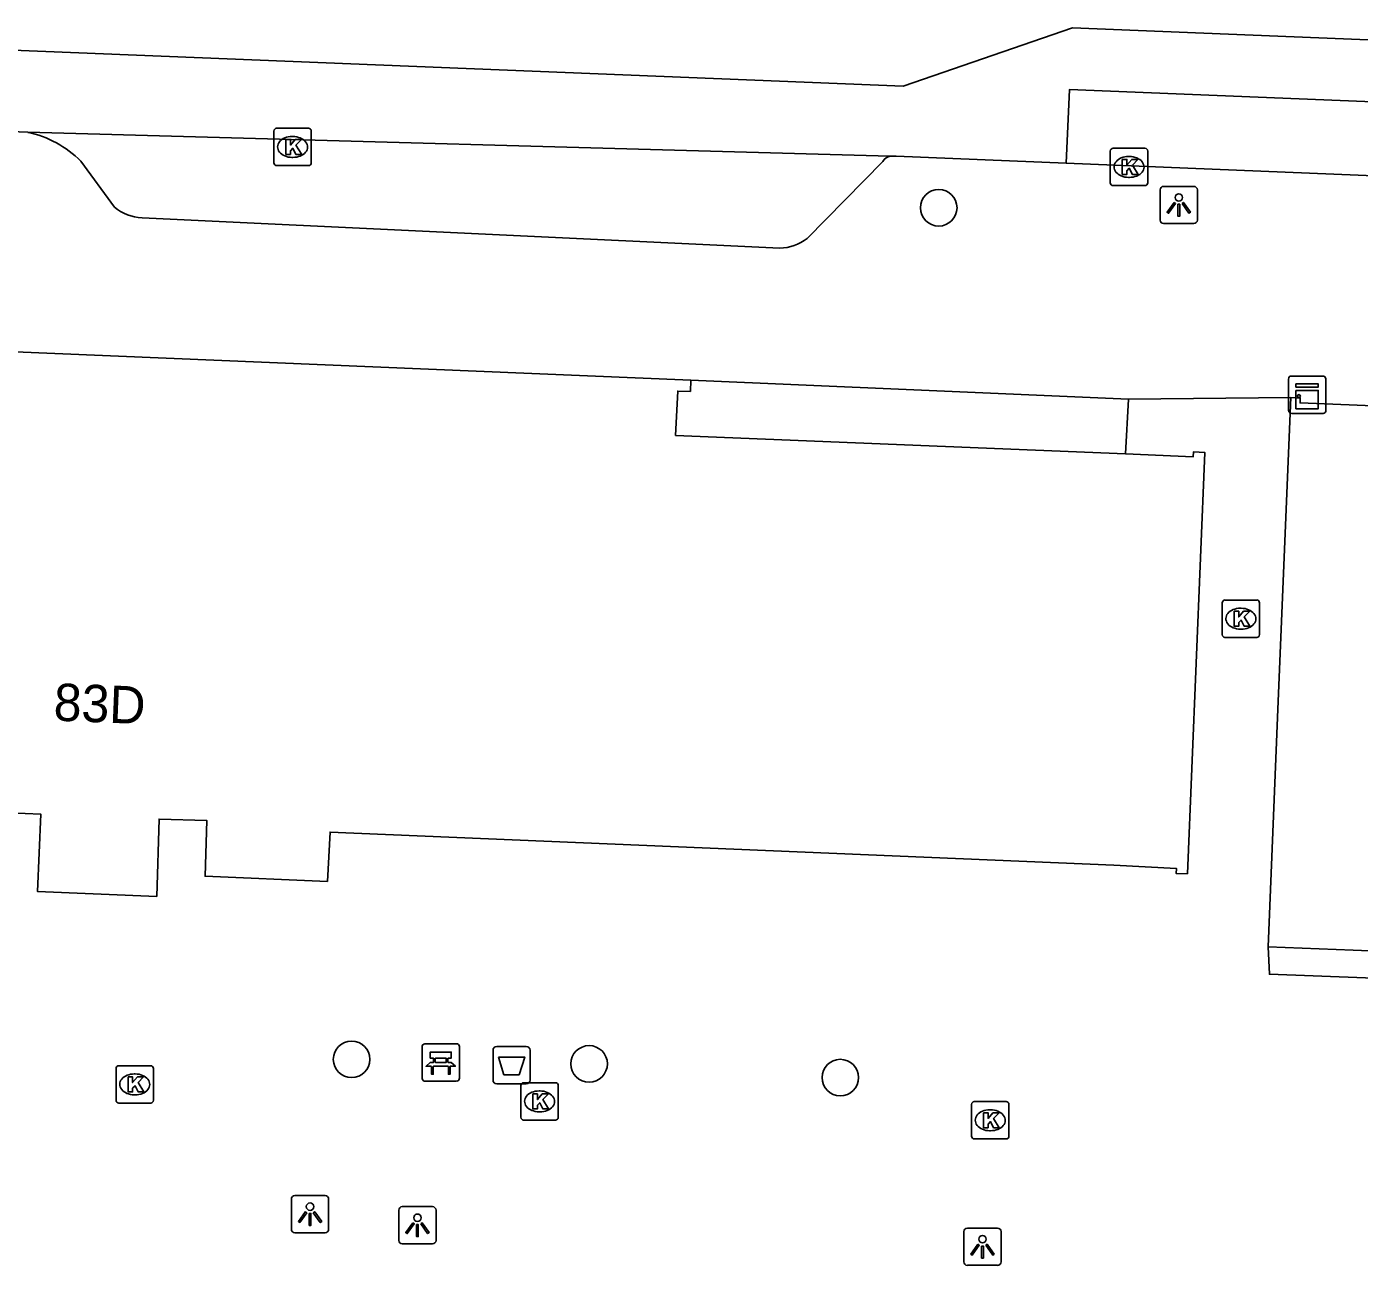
# Model space of a CAD drawing. Extents: x 160891 to 161384, y 386490 to 386907.
# Drawn here: x 161012.2 to 161047.88, y 386870.79 to 386903.93 of the extents above; entities that cross this region are included whole.
import ezdxf

# ---------------------------------------------------------------- set-up
doc = ezdxf.new("R2010")
doc.units = 0
for name, color, linetype in [('IMGEO_Afvalbak', 7, 'Continuous'), ('IMGEO_Bank', 7, 'Continuous'), ('IMGEO_Boom', 7, 'Continuous'), ('IMGEO_Kast', 7, 'Continuous'), ('IMGEO_Kolk', 7, 'Continuous'), ('IMGEO_Lichtpunt', 7, 'Continuous'), ('IMGEO_Pand', 7, 'Continuous'), ('IMGEO_Pand_nummerreeks', 7, 'Continuous'), ('IMGEO_Rijbaan_lokaal_gesloten', 7, 'Continuous'), ('IMGEO_Voetpad_open', 7, 'Continuous')]:
    doc.layers.add(name, color=color, linetype=linetype)

msp = doc.modelspace()

# ---------------------------------------------------------------- linework, layer by layer
at = {"layer": 'IMGEO_Afvalbak'}
for p, q in [((161024.689, 386875.746), (161024.689, 386876.546)), ((161024.689, 386876.546), (161024.689, 386875.746)), ((161024.789, 386876.646), (161025.579, 386876.646)), ((161025.579, 386876.646), (161024.789, 386876.646)), ((161025.679, 386876.546), (161025.679, 386875.746)), ((161025.679, 386875.746), (161025.679, 386876.546)), ((161025.579, 386875.646), (161024.789, 386875.646)), ((161024.789, 386875.646), (161025.579, 386875.646))]:
    msp.add_line(p, q, dxfattribs=at)
msp.add_lwpolyline([(161024.832, 386876.36), (161025.536, 386876.36), (161025.387, 386875.89), (161024.981, 386875.89), (161024.832, 386876.36)], dxfattribs=at)
for centre, start, end in [((161024.789, 386876.546), 90, 180), ((161024.789, 386876.546), 90, 180), ((161025.579, 386876.546), 0, 90), ((161025.579, 386876.546), 360, 90), ((161024.789, 386875.746), 180, 270), ((161024.789, 386875.746), 180, 270), ((161025.579, 386875.746), 270, 0), ((161025.579, 386875.746), 270, 0)]:
    msp.add_arc(centre, 0.1, start, end, dxfattribs=at)
at = {"layer": 'IMGEO_Bank'}
for p, q in [((161022.79, 386875.792), (161022.79, 386876.633)), ((161022.79, 386876.633), (161022.79, 386875.792)), ((161022.865, 386876.717), (161023.706, 386876.717)), ((161023.706, 386876.717), (161022.865, 386876.717)), ((161023.79, 386876.642), (161023.79, 386875.801)), ((161023.79, 386875.801), (161023.79, 386876.642)), ((161023.099, 386876.223), (161023.099, 386876.329)), ((161023.143, 386876.329), (161023.143, 386876.223)), ((161023.431, 386876.335), (161023.149, 386876.335)), ((161023.149, 386876.217), (161023.431, 386876.217)), ((161023.437, 386876.223), (161023.437, 386876.329)), ((161023.481, 386876.329), (161023.481, 386876.223)), ((161023.487, 386876.115), (161023.094, 386876.115)), ((161023.715, 386875.717), (161022.874, 386875.717)), ((161022.874, 386875.717), (161023.715, 386875.717))]:
    msp.add_line(p, q, dxfattribs=at)
for points in [[(161023.093, 386876.335), (161023.007, 386876.335), (161023.007, 386876.496), (161023.57, 386876.496), (161023.57, 386876.335), (161023.487, 386876.335)], [(161023.037, 386876.115), (161022.895, 386876.115), (161023.007, 386876.217), (161023.093, 386876.217)], [(161023.487, 386876.217), (161023.57, 386876.217), (161023.682, 386876.115), (161023.543, 386876.115)], [(161023.087, 386876.108), (161023.087, 386875.901), (161023.044, 386875.901), (161023.044, 386876.108)], [(161023.537, 386876.108), (161023.537, 386875.901), (161023.493, 386875.901), (161023.493, 386876.108)]]:
    msp.add_lwpolyline(points, dxfattribs=at)
for centre, radius, start, end in [((161022.868, 386876.639), 0.0779, 92.4484, 184.2845), ((161022.868, 386876.639), 0.0779, 92.4484, 184.2845), ((161023.712, 386876.639), 0.0779, 2.4484, 94.2845), ((161023.712, 386876.639), 0.0779, 2.4484, 94.2845), ((161023.092, 386876.328), 0.00671, 2.8957, 87.1043), ((161023.092, 386876.224), 0.00671, 272.8957, 357.1043), ((161023.149, 386876.328), 0.00671, 92.8957, 177.1043), ((161023.149, 386876.224), 0.00671, 182.8957, 267.1043), ((161023.431, 386876.328), 0.00671, 2.8957, 87.1043), ((161023.431, 386876.224), 0.00671, 272.8957, 357.1043), ((161023.488, 386876.328), 0.00671, 92.8957, 177.1043), ((161023.488, 386876.224), 0.00671, 182.8957, 267.1043), ((161022.868, 386875.795), 0.0779, 182.4484, 274.2845), ((161022.868, 386875.795), 0.0779, 182.4484, 274.2845), ((161023.037, 386876.108), 0.00671, 2.8957, 87.1043), ((161023.094, 386876.108), 0.00671, 92.8957, 177.1043), ((161023.486, 386876.108), 0.00671, 2.8957, 87.1043), ((161023.543, 386876.108), 0.00671, 92.8957, 177.1043), ((161023.712, 386875.795), 0.0779, 272.4484, 4.2845), ((161023.712, 386875.795), 0.0779, 272.4484, 4.2845)]:
    msp.add_arc(centre, radius, start, end, dxfattribs=at)
at = {"layer": 'IMGEO_Boom'}
for centre in [(161036.621, 386899.089), (161020.902, 386876.302), (161027.261, 386876.181), (161033.985, 386875.814)]:
    msp.add_circle(centre, 0.489, dxfattribs=at)
at = {"layer": 'IMGEO_Kast'}
for p, q in [((161045.986, 386893.662), (161045.986, 386894.503)), ((161045.986, 386894.503), (161045.986, 386893.662)), ((161046.061, 386894.587), (161046.902, 386894.587)), ((161046.902, 386894.587), (161046.061, 386894.587)), ((161046.986, 386894.512), (161046.986, 386893.671)), ((161046.986, 386893.671), (161046.986, 386894.512)), ((161046.911, 386893.587), (161046.07, 386893.587)), ((161046.07, 386893.587), (161046.911, 386893.587))]:
    msp.add_line(p, q, dxfattribs=at)
for points in [[(161046.181, 386894.377), (161046.781, 386894.377), (161046.781, 386894.292), (161046.181, 386894.292), (161046.181, 386894.377)], [(161046.181, 386894.202), (161046.781, 386894.202), (161046.781, 386893.713), (161046.181, 386893.713), (161046.181, 386894.202)]]:
    msp.add_lwpolyline(points, dxfattribs=at)
msp.add_circle((161046.265, 386894.051), 0.0377, dxfattribs=at)
for centre, start, end in [((161046.064, 386894.509), 92.4484, 184.2845), ((161046.064, 386894.509), 92.4484, 184.2845), ((161046.908, 386894.509), 2.4484, 94.2845), ((161046.908, 386894.509), 2.4484, 94.2845), ((161046.064, 386893.665), 182.4484, 274.2845), ((161046.064, 386893.665), 182.4484, 274.2845), ((161046.908, 386893.665), 272.4484, 4.2845), ((161046.908, 386893.665), 272.4484, 4.2845)]:
    msp.add_arc(centre, 0.0779, start, end, dxfattribs=at)
at = {"layer": 'IMGEO_Kolk'}
for p, q in [((161018.821, 386900.29), (161018.821, 386901.142)), ((161018.896, 386901.216), (161019.748, 386901.216)), ((161019.822, 386901.142), (161019.822, 386900.29)), ((161019.309, 386900.996), (161019.334, 386900.996)), ((161019.332, 386900.436), (161019.307, 386900.436)), ((161041.214, 386899.755), (161041.214, 386900.607)), ((161041.289, 386900.681), (161042.141, 386900.681)), ((161041.702, 386900.461), (161041.727, 386900.461)), ((161042.215, 386900.607), (161042.215, 386899.755)), ((161019.748, 386900.216), (161018.896, 386900.216)), ((161041.725, 386899.901), (161041.7, 386899.901)), ((161042.141, 386899.681), (161041.289, 386899.681)), ((161044.208, 386887.667), (161044.208, 386888.519)), ((161044.283, 386888.593), (161045.135, 386888.593)), ((161044.696, 386888.373), (161044.721, 386888.373)), ((161045.209, 386888.519), (161045.209, 386887.667)), ((161045.135, 386887.593), (161044.283, 386887.593)), ((161044.719, 386887.813), (161044.694, 386887.813)), ((161014.597, 386875.206), (161014.597, 386876.058)), ((161014.672, 386876.132), (161015.524, 386876.132)), ((161015.085, 386875.912), (161015.11, 386875.912)), ((161015.598, 386876.058), (161015.598, 386875.206)), ((161025.433, 386874.751), (161025.433, 386875.603)), ((161025.508, 386875.677), (161026.36, 386875.677)), ((161025.921, 386875.457), (161025.946, 386875.457)), ((161026.434, 386875.603), (161026.434, 386874.751)), ((161015.524, 386875.132), (161014.672, 386875.132)), ((161015.108, 386875.352), (161015.083, 386875.352)), ((161037.498, 386874.245), (161037.498, 386875.097)), ((161037.573, 386875.171), (161038.425, 386875.171)), ((161038.499, 386875.097), (161038.499, 386874.245)), ((161025.944, 386874.897), (161025.919, 386874.897)), ((161037.986, 386874.951), (161038.011, 386874.951)), ((161026.36, 386874.677), (161025.508, 386874.677)), ((161038.009, 386874.391), (161037.984, 386874.391)), ((161038.425, 386874.171), (161037.573, 386874.171))]:
    msp.add_line(p, q, dxfattribs=at)
for points in [[(161018.821, 386900.29), (161018.821, 386901.142)], [(161018.896, 386901.216), (161019.748, 386901.216)], [(161019.822, 386901.142), (161019.822, 386900.29)], [(161019.142, 386900.916), (161019.265, 386900.916), (161019.265, 386900.765), (161019.395, 386900.916), (161019.559, 386900.916), (161019.413, 386900.765), (161019.566, 386900.516), (161019.414, 386900.516), (161019.329, 386900.68), (161019.265, 386900.613), (161019.265, 386900.516), (161019.142, 386900.516), (161019.142, 386900.916)], [(161041.214, 386899.755), (161041.214, 386900.607)], [(161041.289, 386900.681), (161042.141, 386900.681)], [(161042.215, 386900.607), (161042.215, 386899.755)], [(161019.748, 386900.216), (161018.896, 386900.216)], [(161041.535, 386900.381), (161041.658, 386900.381), (161041.658, 386900.23), (161041.788, 386900.381), (161041.952, 386900.381), (161041.806, 386900.23), (161041.959, 386899.981), (161041.807, 386899.981), (161041.722, 386900.145), (161041.658, 386900.078), (161041.658, 386899.981), (161041.535, 386899.981), (161041.535, 386900.381)], [(161042.141, 386899.681), (161041.289, 386899.681)], [(161044.208, 386887.667), (161044.208, 386888.519)], [(161044.283, 386888.593), (161045.135, 386888.593)], [(161044.529, 386888.293), (161044.652, 386888.293), (161044.652, 386888.142), (161044.782, 386888.293), (161044.946, 386888.293), (161044.8, 386888.142), (161044.953, 386887.893), (161044.801, 386887.893), (161044.716, 386888.057), (161044.652, 386887.99), (161044.652, 386887.893), (161044.529, 386887.893), (161044.529, 386888.293)], [(161045.209, 386888.519), (161045.209, 386887.667)], [(161045.135, 386887.593), (161044.283, 386887.593)], [(161014.597, 386875.206), (161014.597, 386876.058)], [(161014.672, 386876.132), (161015.524, 386876.132)], [(161014.918, 386875.832), (161015.041, 386875.832), (161015.041, 386875.681), (161015.171, 386875.832), (161015.335, 386875.832), (161015.189, 386875.681), (161015.342, 386875.432), (161015.19, 386875.432), (161015.105, 386875.596), (161015.041, 386875.529), (161015.041, 386875.432), (161014.918, 386875.432), (161014.918, 386875.832)], [(161015.598, 386876.058), (161015.598, 386875.206)], [(161025.433, 386874.751), (161025.433, 386875.603)], [(161025.508, 386875.677), (161026.36, 386875.677)], [(161026.434, 386875.603), (161026.434, 386874.751)], [(161015.524, 386875.132), (161014.672, 386875.132)], [(161025.754, 386875.377), (161025.877, 386875.377), (161025.877, 386875.226), (161026.007, 386875.377), (161026.171, 386875.377), (161026.025, 386875.226), (161026.178, 386874.977), (161026.026, 386874.977), (161025.941, 386875.141), (161025.877, 386875.074), (161025.877, 386874.977), (161025.754, 386874.977), (161025.754, 386875.377)], [(161037.498, 386874.245), (161037.498, 386875.097)], [(161037.573, 386875.171), (161038.425, 386875.171)], [(161038.499, 386875.097), (161038.499, 386874.245)], [(161037.819, 386874.871), (161037.942, 386874.871), (161037.942, 386874.72), (161038.072, 386874.871), (161038.236, 386874.871), (161038.09, 386874.72), (161038.243, 386874.471), (161038.091, 386874.471), (161038.006, 386874.635), (161037.942, 386874.568), (161037.942, 386874.471), (161037.819, 386874.471), (161037.819, 386874.871)], [(161026.36, 386874.677), (161025.508, 386874.677)], [(161038.425, 386874.171), (161037.573, 386874.171)]]:
    msp.add_lwpolyline(points, dxfattribs=at)
for centre, start, end in [((161018.898, 386901.14), 91.552, 178.448), ((161018.898, 386901.14), 91.552, 178.448), ((161019.746, 386901.14), 1.552, 88.448), ((161019.746, 386901.14), 1.552, 88.448), ((161041.291, 386900.605), 91.552, 178.448), ((161041.291, 386900.605), 91.552, 178.448), ((161042.139, 386900.605), 1.552, 88.448), ((161042.139, 386900.605), 1.552, 88.448), ((161018.898, 386900.292), 181.552, 268.448), ((161018.898, 386900.292), 181.552, 268.448), ((161019.746, 386900.292), 271.552, 358.448), ((161019.746, 386900.292), 271.552, 358.448), ((161041.291, 386899.757), 181.552, 268.448), ((161041.291, 386899.757), 181.552, 268.448), ((161042.139, 386899.757), 271.552, 358.448), ((161042.139, 386899.757), 271.552, 358.448), ((161044.285, 386888.517), 91.552, 178.448), ((161044.285, 386888.517), 91.552, 178.448), ((161045.133, 386888.517), 1.552, 88.448), ((161045.133, 386888.517), 1.552, 88.448), ((161044.285, 386887.669), 181.552, 268.448), ((161044.285, 386887.669), 181.552, 268.448), ((161045.133, 386887.669), 271.552, 358.448), ((161045.133, 386887.669), 271.552, 358.448), ((161014.674, 386876.056), 91.552, 178.448), ((161014.674, 386876.056), 91.552, 178.448), ((161015.522, 386876.056), 1.552, 88.448), ((161015.522, 386876.056), 1.552, 88.448), ((161025.51, 386875.601), 91.552, 178.448), ((161025.51, 386875.601), 91.552, 178.448), ((161026.358, 386875.601), 1.552, 88.448), ((161026.358, 386875.601), 1.552, 88.448), ((161014.674, 386875.208), 181.552, 268.448), ((161014.674, 386875.208), 181.552, 268.448), ((161015.522, 386875.208), 271.552, 358.448), ((161015.522, 386875.208), 271.552, 358.448), ((161037.575, 386875.095), 91.552, 178.448), ((161037.575, 386875.095), 91.552, 178.448), ((161038.423, 386875.095), 1.552, 88.448), ((161038.423, 386875.095), 1.552, 88.448), ((161025.51, 386874.753), 181.552, 268.448), ((161025.51, 386874.753), 181.552, 268.448), ((161026.358, 386874.753), 271.552, 358.448), ((161026.358, 386874.753), 271.552, 358.448), ((161037.575, 386874.247), 181.552, 268.448), ((161037.575, 386874.247), 181.552, 268.448), ((161038.423, 386874.247), 271.552, 358.448), ((161038.423, 386874.247), 271.552, 358.448)]:
    msp.add_arc(centre, 0.0765, start, end, dxfattribs=at)
for centre, major_axis, ratio, start_param, end_param in [((161019.308, 386900.716), (-0.387, 0.002), 0.722429, 4.712389, 7.853982), ((161019.333, 386900.716), (-0.39, 0.002), 0.717154, 1.570796, 4.712389), ((161041.701, 386900.181), (-0.387, 0.002), 0.722429, 4.712389, 7.853982), ((161041.726, 386900.181), (-0.39, 0.002), 0.717154, 1.570796, 4.712389), ((161044.695, 386888.093), (-0.387, 0.002), 0.722429, 4.712389, 7.853982), ((161044.72, 386888.093), (-0.39, 0.002), 0.717154, 1.570796, 4.712389), ((161015.084, 386875.632), (-0.387, 0.002), 0.722429, 4.712389, 7.853982), ((161015.109, 386875.632), (-0.39, 0.002), 0.717154, 1.570796, 4.712389), ((161025.92, 386875.177), (-0.387, 0.002), 0.722429, 4.712389, 7.853982), ((161025.945, 386875.177), (-0.39, 0.002), 0.717154, 1.570796, 4.712389), ((161037.985, 386874.671), (-0.387, 0.002), 0.722429, 4.712389, 7.853982), ((161038.01, 386874.671), (-0.39, 0.002), 0.717154, 1.570796, 4.712389)]:
    msp.add_ellipse(centre, major_axis=major_axis, ratio=ratio, start_param=start_param, end_param=end_param, dxfattribs=at)
at = {"layer": 'IMGEO_Lichtpunt'}
for p, q in [((161042.548, 386899.567), (161042.548, 386898.76)), ((161042.548, 386899.567), (161042.548, 386898.76)), ((161043.45, 386899.662), (161042.642, 386899.662)), ((161043.45, 386899.662), (161042.642, 386899.662)), ((161043.544, 386898.76), (161043.544, 386899.567)), ((161043.544, 386898.76), (161043.544, 386899.567)), ((161042.642, 386898.666), (161043.45, 386898.666)), ((161042.642, 386898.666), (161043.45, 386898.666)), ((161020.193, 386872.657), (161019.385, 386872.657)), ((161020.193, 386872.657), (161019.385, 386872.657)), ((161019.291, 386872.562), (161019.291, 386871.755)), ((161019.291, 386872.562), (161019.291, 386871.755)), ((161020.287, 386871.755), (161020.287, 386872.562)), ((161020.287, 386871.755), (161020.287, 386872.562)), ((161022.166, 386872.265), (161022.166, 386871.458)), ((161022.166, 386872.265), (161022.166, 386871.458)), ((161023.068, 386872.36), (161022.26, 386872.36)), ((161023.068, 386872.36), (161022.26, 386872.36)), ((161023.162, 386871.458), (161023.162, 386872.265)), ((161023.162, 386871.458), (161023.162, 386872.265)), ((161019.385, 386871.661), (161020.193, 386871.661)), ((161019.385, 386871.661), (161020.193, 386871.661)), ((161037.293, 386871.691), (161037.293, 386870.884)), ((161037.293, 386871.691), (161037.293, 386870.884)), ((161038.195, 386871.786), (161037.387, 386871.786)), ((161038.195, 386871.786), (161037.387, 386871.786)), ((161038.289, 386870.884), (161038.289, 386871.691)), ((161038.289, 386870.884), (161038.289, 386871.691)), ((161022.26, 386871.364), (161023.068, 386871.364)), ((161022.26, 386871.364), (161023.068, 386871.364)), ((161037.387, 386870.79), (161038.195, 386870.79)), ((161037.387, 386870.79), (161038.195, 386870.79))]:
    msp.add_line(p, q, dxfattribs=at)
for points in [[(161042.922, 386899.231), (161042.961, 386899.203), (161042.773, 386898.941), (161042.735, 386898.968), (161042.922, 386899.231)], [(161043.024, 386899.183), (161043.071, 386899.183), (161043.071, 386898.861), (161043.024, 386898.861), (161043.024, 386899.183)], [(161043.134, 386899.203), (161043.172, 386899.23), (161043.359, 386898.968), (161043.32, 386898.94), (161043.134, 386899.203)], [(161019.665, 386872.226), (161019.704, 386872.198), (161019.516, 386871.936), (161019.478, 386871.963), (161019.665, 386872.226)], [(161019.877, 386872.198), (161019.915, 386872.225), (161020.102, 386871.963), (161020.063, 386871.935), (161019.877, 386872.198)], [(161019.767, 386872.178), (161019.814, 386872.178), (161019.814, 386871.856), (161019.767, 386871.856), (161019.767, 386872.178)], [(161022.54, 386871.929), (161022.579, 386871.901), (161022.391, 386871.639), (161022.353, 386871.666), (161022.54, 386871.929)], [(161022.642, 386871.881), (161022.689, 386871.881), (161022.689, 386871.559), (161022.642, 386871.559), (161022.642, 386871.881)], [(161022.752, 386871.901), (161022.79, 386871.928), (161022.977, 386871.666), (161022.938, 386871.638), (161022.752, 386871.901)], [(161037.667, 386871.355), (161037.706, 386871.327), (161037.518, 386871.065), (161037.48, 386871.092), (161037.667, 386871.355)], [(161037.769, 386871.307), (161037.816, 386871.307), (161037.816, 386870.985), (161037.769, 386870.985), (161037.769, 386871.307)], [(161037.879, 386871.327), (161037.917, 386871.354), (161038.104, 386871.092), (161038.065, 386871.064), (161037.879, 386871.327)]]:
    msp.add_lwpolyline(points, dxfattribs=at)
for centre in [(161043.047, 386899.365), (161019.79, 386872.36), (161022.665, 386872.063), (161037.792, 386871.489)]:
    msp.add_circle(centre, 0.0994, dxfattribs=at)
for centre, start, end in [((161042.642, 386899.567), 90, 180), ((161042.642, 386899.567), 90, 180), ((161043.45, 386899.567), 0, 90), ((161043.45, 386899.567), 0, 90), ((161042.642, 386898.76), 180, 270), ((161042.642, 386898.76), 180, 270), ((161043.45, 386898.76), 270, 0), ((161043.45, 386898.76), 270, 360), ((161019.385, 386872.562), 90, 180), ((161019.385, 386872.562), 90, 180), ((161020.193, 386872.562), 0, 90), ((161020.193, 386872.562), 0, 90), ((161022.26, 386872.265), 90, 180), ((161022.26, 386872.265), 90, 180), ((161023.068, 386872.265), 0, 90), ((161023.068, 386872.265), 0, 90), ((161019.385, 386871.755), 180, 270), ((161019.385, 386871.755), 180, 270), ((161020.193, 386871.755), 270, 0), ((161020.193, 386871.755), 270, 360), ((161037.387, 386871.691), 90, 180), ((161037.387, 386871.691), 90, 180), ((161038.195, 386871.691), 0, 90), ((161038.195, 386871.691), 0, 90), ((161022.26, 386871.458), 180, 270), ((161022.26, 386871.458), 180, 270), ((161023.068, 386871.458), 270, 0), ((161023.068, 386871.458), 270, 360), ((161037.387, 386870.884), 180, 270), ((161037.387, 386870.884), 180, 270), ((161038.195, 386870.884), 270, 0), ((161038.195, 386870.884), 270, 360)]:
    msp.add_arc(centre, 0.0946, start, end, dxfattribs=at)
at = {"layer": 'IMGEO_Pand'}
for points in [[(161029.981, 386894.476), (161004.65, 386895.537), (160993.236, 386896.016)], [(161041.618, 386892.502), (161029.577, 386892.999), (161029.633, 386894.185), (161029.973, 386894.176), (161029.981, 386894.476)], [(161046.043, 386894.008), (161045.711, 386885.882), (161045.442, 386879.308)], [(161113.143, 386891.17), (161097.194, 386891.813), (161080.645, 386892.481), (161055.667, 386893.489), (161046.293, 386893.867), (161046.299, 386893.997), (161046.043, 386894.008)], [(161041.618, 386892.502), (161043.434, 386892.427), (161043.44, 386892.556), (161043.741, 386892.544), (161043.277, 386881.267), (161042.977, 386881.279), (161042.983, 386881.409), (161041.31, 386881.494), (161020.328, 386882.383), (161020.255, 386881.065), (161016.978, 386881.201), (161017.026, 386882.693), (161015.75, 386882.733), (161015.686, 386880.661), (161012.496, 386880.789), (161012.587, 386882.859), (161011.314, 386882.915), (161011.271, 386881.437), (161000, 386881.915), (160992.691, 386882.225), (160992.717, 386882.523), (160993.063, 386882.501), (160993.1, 386883.616)], [(161045.442, 386879.308), (161047.716, 386879.222), (161049.049, 386879.172)]]:
    msp.add_lwpolyline(points, dxfattribs=at)
at = {"layer": 'IMGEO_Rijbaan_lokaal_gesloten'}
for points in [[(161112.299, 386900.982), (161040.205, 386903.901), (161035.665, 386902.345), (160996.157, 386903.935)], [(161040.028, 386900.281), (161040.12, 386902.25), (161064.059, 386901.284)], [(160994.092, 386902.091), (160996.449, 386901.746), (160999.189, 386901.61), (161000, 386901.579), (161012.233, 386901.108)], [(161012.233, 386901.108), (161035.324, 386900.473)], [(161035.324, 386900.473), (161035.479, 386900.468), (161040.028, 386900.281)]]:
    msp.add_lwpolyline(points, dxfattribs=at)
at = {"layer": 'IMGEO_Voetpad_open'}
for points in [[(161013.653, 386900.34), (161014.554, 386899.103)], [(161033.101, 386898.269), (161035.124, 386900.328)], [(161040.028, 386900.281), (161063.696, 386899.307), (161064.015, 386899.299)], [(161015.294, 386898.823), (161032.364, 386898.006)], [(161029.981, 386894.476), (161035.955, 386894.217), (161041.701, 386893.968)], [(161046.043, 386894.008), (161041.701, 386893.968)], [(161041.701, 386893.968), (161041.618, 386892.502)], [(161049.049, 386879.172), (161049.023, 386878.446), (161048.048, 386878.482), (161045.473, 386878.577), (161045.442, 386879.308)]]:
    msp.add_lwpolyline(points, dxfattribs=at)
for centre, radius, start, end in [((161011.649, 386898.331), 2.837, 45.0654, 78.1215), ((161035.393, 386900.168), 0.313, 102.7, 149.1842), ((161015.337, 386900.055), 1.233, 230.5588, 267.99), ((161032.311, 386899.318), 1.313, 272.3016, 306.9765)]:
    msp.add_arc(centre, radius, start, end, dxfattribs=at)

# ---------------------------------------------------------------- texts
at = {"layer": 'IMGEO_Pand_nummerreeks'}
msp.add_text('83D', height=1, rotation=357.7188, dxfattribs=at).set_placement((161012.914, 386885.368))

doc.saveas('drawing.dxf')
